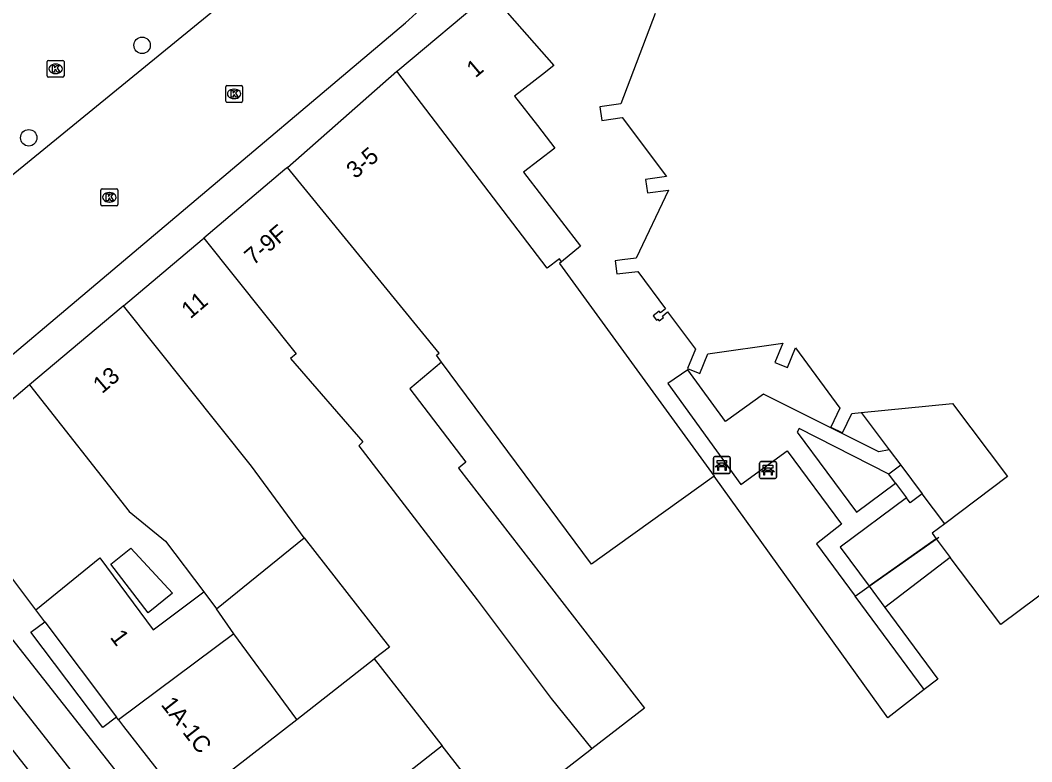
# Model space of a CAD drawing. Extents: x 161087 to 161922, y 382574 to 383873.
# Drawn here: x 161331.9 to 161392, y 383043.5 to 383087.7 of the extents above; entities that cross this region are included whole.
import ezdxf

# ---------------------------------------------------------------- set-up
doc = ezdxf.new("R2010")
doc.units = 0
for name, color, linetype in [('IMGEO_Bank', 7, 'Continuous'), ('IMGEO_Boom', 7, 'Continuous'), ('IMGEO_Erf', 7, 'Continuous'), ('IMGEO_Fietspad_gesloten', 7, 'Continuous'), ('IMGEO_Hek', 7, 'Continuous'), ('IMGEO_Kolk', 7, 'Continuous'), ('IMGEO_OVBaan_gesloten', 7, 'Continuous'), ('IMGEO_Pand', 7, 'Continuous'), ('IMGEO_Pand_nummerreeks', 7, 'Continuous'), ('IMGEO_Rijbaan_lokaal_open', 7, 'Continuous'), ('IMGEO_Voetpad_op_trap', 7, 'Continuous'), ('IMGEO_Voetpad_open', 7, 'Continuous')]:
    doc.layers.add(name, color=color, linetype=linetype)

msp = doc.modelspace()

# ---------------------------------------------------------------- linework, layer by layer
at = {"layer": 'IMGEO_Bank'}
for p, q in [((161373.128, 383060.772), (161373.128, 383061.613)), ((161373.128, 383061.613), (161373.128, 383060.772)), ((161373.203, 383061.697), (161374.044, 383061.697)), ((161374.044, 383061.697), (161373.203, 383061.697)), ((161373.437, 383061.203), (161373.437, 383061.309)), ((161373.481, 383061.309), (161373.481, 383061.203)), ((161373.769, 383061.315), (161373.487, 383061.315)), ((161373.487, 383061.197), (161373.769, 383061.197)), ((161373.775, 383061.203), (161373.775, 383061.309)), ((161373.819, 383061.309), (161373.819, 383061.203)), ((161374.128, 383061.622), (161374.128, 383060.781)), ((161374.128, 383060.781), (161374.128, 383061.622)), ((161375.873, 383060.476), (161375.873, 383061.317)), ((161375.873, 383061.317), (161375.873, 383060.476)), ((161375.948, 383061.401), (161376.789, 383061.401)), ((161376.789, 383061.401), (161375.948, 383061.401)), ((161376.873, 383061.326), (161376.873, 383060.485)), ((161376.873, 383060.485), (161376.873, 383061.326)), ((161374.053, 383060.697), (161373.212, 383060.697)), ((161373.212, 383060.697), (161374.053, 383060.697)), ((161373.825, 383061.095), (161373.432, 383061.095)), ((161376.57, 383060.799), (161376.177, 383060.799)), ((161376.182, 383060.907), (161376.182, 383061.013)), ((161376.226, 383061.013), (161376.226, 383060.907)), ((161376.514, 383061.019), (161376.232, 383061.019)), ((161376.232, 383060.901), (161376.514, 383060.901)), ((161376.52, 383060.907), (161376.52, 383061.013)), ((161376.564, 383061.013), (161376.564, 383060.907)), ((161376.798, 383060.401), (161375.957, 383060.401)), ((161375.957, 383060.401), (161376.798, 383060.401))]:
    msp.add_line(p, q, dxfattribs=at)
for points in [[(161373.375, 383061.095), (161373.233, 383061.095), (161373.345, 383061.197), (161373.431, 383061.197)], [(161373.431, 383061.315), (161373.345, 383061.315), (161373.345, 383061.476), (161373.908, 383061.476), (161373.908, 383061.315), (161373.825, 383061.315)], [(161373.825, 383061.197), (161373.908, 383061.197), (161374.02, 383061.095), (161373.881, 383061.095)], [(161376.176, 383061.019), (161376.09, 383061.019), (161376.09, 383061.18), (161376.653, 383061.18), (161376.653, 383061.019), (161376.57, 383061.019)], [(161373.425, 383061.088), (161373.425, 383060.881), (161373.382, 383060.881), (161373.382, 383061.088)], [(161373.875, 383061.088), (161373.875, 383060.881), (161373.831, 383060.881), (161373.831, 383061.088)], [(161376.12, 383060.799), (161375.978, 383060.799), (161376.09, 383060.901), (161376.176, 383060.901)], [(161376.17, 383060.792), (161376.17, 383060.585), (161376.127, 383060.585), (161376.127, 383060.792)], [(161376.57, 383060.901), (161376.653, 383060.901), (161376.765, 383060.799), (161376.626, 383060.799)], [(161376.62, 383060.792), (161376.62, 383060.585), (161376.576, 383060.585), (161376.576, 383060.792)]]:
    msp.add_lwpolyline(points, dxfattribs=at)
for centre, radius, start, end in [((161373.206, 383061.619), 0.0779, 92.4484, 184.28452), ((161373.206, 383061.619), 0.0779, 92.4484, 184.28452), ((161373.43, 383061.308), 0.00671, 2.89567, 87.10433), ((161373.43, 383061.204), 0.00671, 272.89567, 357.10433), ((161373.487, 383061.308), 0.00671, 92.89567, 177.10433), ((161373.487, 383061.204), 0.00671, 182.89567, 267.10433), ((161373.769, 383061.308), 0.00671, 2.89567, 87.10433), ((161373.769, 383061.204), 0.00671, 272.89567, 357.10433), ((161373.826, 383061.308), 0.00671, 92.89567, 177.10433), ((161373.826, 383061.204), 0.00671, 182.89567, 267.10433), ((161374.05, 383061.619), 0.0779, 2.4484, 94.28452), ((161374.05, 383061.619), 0.0779, 2.4484, 94.28452), ((161375.951, 383061.323), 0.0779, 92.4484, 184.28452), ((161375.951, 383061.323), 0.0779, 92.4484, 184.28452), ((161376.795, 383061.323), 0.0779, 2.4484, 94.28452), ((161376.795, 383061.323), 0.0779, 2.4484, 94.28452), ((161373.206, 383060.775), 0.0779, 182.4484, 274.28452), ((161373.206, 383060.775), 0.0779, 182.4484, 274.28452), ((161373.375, 383061.088), 0.00671, 2.89567, 87.10433), ((161373.432, 383061.088), 0.00671, 92.89567, 177.10433), ((161373.824, 383061.088), 0.00671, 2.89567, 87.10433), ((161373.881, 383061.088), 0.00671, 92.89567, 177.10433), ((161374.05, 383060.775), 0.0779, 272.4484, 4.28452), ((161374.05, 383060.775), 0.0779, 272.4484, 4.28452), ((161376.12, 383060.792), 0.00671, 2.89567, 87.10433), ((161376.177, 383060.792), 0.00671, 92.89567, 177.10433), ((161376.175, 383061.012), 0.00671, 2.89567, 87.10433), ((161376.175, 383060.908), 0.00671, 272.89567, 357.10433), ((161376.232, 383061.012), 0.00671, 92.89567, 177.10433), ((161376.232, 383060.908), 0.00671, 182.89567, 267.10433), ((161376.514, 383061.012), 0.00671, 2.89567, 87.10433), ((161376.514, 383060.908), 0.00671, 272.89567, 357.10433), ((161376.571, 383061.012), 0.00671, 92.89567, 177.10433), ((161376.571, 383060.908), 0.00671, 182.89567, 267.10433), ((161376.569, 383060.792), 0.00671, 2.89567, 87.10433), ((161376.626, 383060.792), 0.00671, 92.89567, 177.10433), ((161375.951, 383060.479), 0.0779, 182.4484, 274.28452), ((161375.951, 383060.479), 0.0779, 182.4484, 274.28452), ((161376.795, 383060.479), 0.0779, 272.4484, 4.28452), ((161376.795, 383060.479), 0.0779, 272.4484, 4.28452)]:
    msp.add_arc(centre, radius, start, end, dxfattribs=at)
at = {"layer": 'IMGEO_Boom'}
for centre in [(161339.171, 383086.168), (161332.433, 383080.665)]:
    msp.add_circle(centre, 0.489, dxfattribs=at)
at = {"layer": 'IMGEO_Erf'}
for points in [[(161385.659, 383047.841), (161383.485, 383046.163), (161373.165, 383060.545)], [(161386.374, 383056.804), (161382.388, 383053.982)], [(161387.204, 383055.697), (161383.319, 383052.72)]]:
    msp.add_lwpolyline(points, dxfattribs=at)
at = {"layer": 'IMGEO_Fietspad_gesloten'}
for points in [[(161412.674, 382945.831), (161395.778, 382967.851), (161371.138, 383000), (161360.861, 383013.409), (161355.304, 383020.491), (161354.659, 383021.314), (161325.561, 383058.315)], [(161323.08, 383057.943), (161323.199, 383057.888), (161324.605, 383056.158), (161359.235, 383012.056), (161368.52, 383000), (161387, 382976.004), (161387.474, 382975.438), (161388.128, 382974.526), (161389.409, 382972.718), (161389.945, 382971.934)]]:
    msp.add_lwpolyline(points, dxfattribs=at)
at = {"layer": 'IMGEO_Hek'}
for points in [[(161382.388, 383053.982), (161386.53, 383056.914)], [(161381.549, 383053.388), (161382.388, 383053.982)]]:
    msp.add_lwpolyline(points, dxfattribs=at)
at = {"layer": 'IMGEO_Kolk'}
for p, q in [((161333.529, 383084.343), (161333.529, 383085.195)), ((161333.604, 383085.269), (161334.456, 383085.269)), ((161334.53, 383085.195), (161334.53, 383084.343)), ((161334.017, 383085.049), (161334.042, 383085.049)), ((161334.456, 383084.269), (161333.604, 383084.269)), ((161334.04, 383084.489), (161334.015, 383084.489)), ((161344.139, 383082.848), (161344.139, 383083.7)), ((161344.214, 383083.774), (161345.066, 383083.774)), ((161344.627, 383083.554), (161344.652, 383083.554)), ((161345.14, 383083.7), (161345.14, 383082.848)), ((161345.066, 383082.774), (161344.214, 383082.774)), ((161344.65, 383082.994), (161344.625, 383082.994)), ((161336.722, 383076.698), (161336.722, 383077.55)), ((161336.797, 383077.624), (161337.649, 383077.624)), ((161337.21, 383077.404), (161337.235, 383077.404)), ((161337.723, 383077.55), (161337.723, 383076.698)), ((161337.233, 383076.844), (161337.208, 383076.844)), ((161337.649, 383076.624), (161336.797, 383076.624))]:
    msp.add_line(p, q, dxfattribs=at)
for points in [[(161333.529, 383084.343), (161333.529, 383085.195)], [(161333.604, 383085.269), (161334.456, 383085.269)], [(161334.53, 383085.195), (161334.53, 383084.343)], [(161333.85, 383084.969), (161333.973, 383084.969), (161333.973, 383084.818), (161334.103, 383084.969), (161334.267, 383084.969), (161334.121, 383084.818), (161334.274, 383084.569), (161334.122, 383084.569), (161334.037, 383084.733), (161333.973, 383084.666), (161333.973, 383084.569), (161333.85, 383084.569), (161333.85, 383084.969)], [(161334.456, 383084.269), (161333.604, 383084.269)], [(161344.139, 383082.848), (161344.139, 383083.7)], [(161344.214, 383083.774), (161345.066, 383083.774)], [(161344.46, 383083.474), (161344.583, 383083.474), (161344.583, 383083.323), (161344.713, 383083.474), (161344.877, 383083.474), (161344.731, 383083.323), (161344.884, 383083.074), (161344.732, 383083.074), (161344.647, 383083.238), (161344.583, 383083.171), (161344.583, 383083.074), (161344.46, 383083.074), (161344.46, 383083.474)], [(161345.14, 383083.7), (161345.14, 383082.848)], [(161345.066, 383082.774), (161344.214, 383082.774)], [(161336.722, 383076.698), (161336.722, 383077.55)], [(161336.797, 383077.624), (161337.649, 383077.624)], [(161337.723, 383077.55), (161337.723, 383076.698)], [(161337.043, 383077.324), (161337.166, 383077.324), (161337.166, 383077.173), (161337.296, 383077.324), (161337.46, 383077.324), (161337.314, 383077.173), (161337.467, 383076.924), (161337.315, 383076.924), (161337.23, 383077.088), (161337.166, 383077.021), (161337.166, 383076.924), (161337.043, 383076.924), (161337.043, 383077.324)], [(161337.649, 383076.624), (161336.797, 383076.624)]]:
    msp.add_lwpolyline(points, dxfattribs=at)
for centre, start, end in [((161333.606, 383085.193), 91.55205, 178.44795), ((161333.606, 383085.193), 91.55205, 178.44795), ((161334.454, 383085.193), 1.55205, 88.44795), ((161334.454, 383085.193), 1.55205, 88.44795), ((161333.606, 383084.345), 181.55205, 268.44795), ((161333.606, 383084.345), 181.55205, 268.44795), ((161334.454, 383084.345), 271.55205, 358.44795), ((161334.454, 383084.345), 271.55205, 358.44795), ((161344.216, 383083.698), 91.55205, 178.44795), ((161344.216, 383083.698), 91.55205, 178.44795), ((161345.064, 383083.698), 1.55205, 88.44795), ((161345.064, 383083.698), 1.55205, 88.44795), ((161344.216, 383082.85), 181.55205, 268.44795), ((161344.216, 383082.85), 181.55205, 268.44795), ((161345.064, 383082.85), 271.55205, 358.44795), ((161345.064, 383082.85), 271.55205, 358.44795), ((161336.799, 383077.548), 91.55205, 178.44795), ((161336.799, 383077.548), 91.55205, 178.44795), ((161337.647, 383077.548), 1.55205, 88.44795), ((161337.647, 383077.548), 1.55205, 88.44795), ((161336.799, 383076.7), 181.55205, 268.44795), ((161336.799, 383076.7), 181.55205, 268.44795), ((161337.647, 383076.7), 271.55205, 358.44795), ((161337.647, 383076.7), 271.55205, 358.44795)]:
    msp.add_arc(centre, 0.0765, start, end, dxfattribs=at)
for centre, major_axis, ratio, start_param, end_param in [((161334.016, 383084.769), (-0.387, 0.002), 0.722429, 4.712389, 7.853982), ((161334.041, 383084.769), (-0.39, 0.002), 0.717154, 1.570796, 4.712389), ((161344.626, 383083.274), (-0.387, 0.002), 0.722429, 4.712389, 7.853982), ((161344.651, 383083.274), (-0.39, 0.002), 0.717154, 1.570796, 4.712389), ((161337.209, 383077.124), (-0.387, 0.002), 0.722429, 4.712389, 7.853982), ((161337.234, 383077.124), (-0.39, 0.002), 0.717154, 1.570796, 4.712389)]:
    msp.add_ellipse(centre, major_axis=major_axis, ratio=ratio, start_param=start_param, end_param=end_param, dxfattribs=at)
at = {"layer": 'IMGEO_OVBaan_gesloten'}
msp.add_lwpolyline([(161325.438, 383051.889), (161366.206, 383000), (161367.365, 382998.522)], dxfattribs=at)
at = {"layer": 'IMGEO_Pand'}
for points in [[(161354.318, 383084.62), (161354.364, 383084.66), (161359.849, 383089.298), (161359.918, 383089.219)], [(161360.142, 383088.963), (161363.648, 383084.959), (161362.972, 383084.424), (161361.312, 383083.146), (161362.666, 383081.388), (161363.693, 383080.054), (161361.831, 383078.62), (161365.218, 383074.222), (161364.102, 383073.291)], [(161369.672, 383088.069), (161367.615, 383082.684), (161366.374, 383082.507), (161366.491, 383081.698), (161367.707, 383081.87), (161370.346, 383078.36), (161369.097, 383078.186), (161369.202, 383077.393), (161370.45, 383077.552), (161368.539, 383073.5), (161367.695, 383073.4), (161367.286, 383073.351), (161367.382, 383072.564), (161368.636, 383072.712), (161370.282, 383070.486), (161369.976, 383070.26), (161369.905, 383070.357), (161369.549, 383070.072), (161369.741, 383069.814), (161369.825, 383069.874), (161369.893, 383069.782), (161370.152, 383069.98), (161370.091, 383070.059), (161370.396, 383070.304), (161372.056, 383068.092), (161371.586, 383066.932), (161372.327, 383066.643), (161372.794, 383067.808), (161377.262, 383068.452), (161376.786, 383067.307), (161377.528, 383066.999), (161378, 383068.171), (161380.648, 383064.59), (161380.099, 383063.452), (161380.806, 383063.112), (161381.357, 383064.263), (161381.903, 383064.319)], [(161347.804, 383078.905), (161354.318, 383084.62)], [(161364.102, 383073.291), (161363.972, 383073.474), (161363.242, 383072.901), (161354.318, 383084.62)], [(161347.804, 383078.905), (161347.663, 383078.781), (161342.835, 383074.693)], [(161356.973, 383067.319), (161356.673, 383067.725), (161356.825, 383067.846), (161347.804, 383078.905)], [(161338.071, 383070.66), (161342.739, 383074.613), (161342.835, 383074.693)], [(161342.835, 383074.693), (161348.322, 383067.806), (161347.987, 383067.529), (161352.289, 383062.57), (161352.053, 383062.349), (161359.093, 383053.183), (161363.477, 383047.313), (161365.909, 383044.313)], [(161364.102, 383073.291), (161363.982, 383073.191), (161373.165, 383060.545)], [(161338.071, 383070.66), (161337.93, 383070.541), (161332.485, 383065.961)], [(161348.807, 383056.868), (161345.668, 383061.123), (161338.071, 383070.66)], [(161356.973, 383067.319), (161355.077, 383065.731), (161358.407, 383061.359), (161357.97, 383061.02), (161369.037, 383046.737), (161365.909, 383044.313)], [(161373.165, 383060.545), (161366.508, 383055.762), (161365.873, 383055.306), (161356.973, 383067.319)], [(161332.485, 383065.961), (161330.317, 383064.136), (161330.489, 383063.928), (161328.256, 383062.101), (161328.085, 383062.31), (161327.199, 383061.585)], [(161332.485, 383065.961), (161338.407, 383058.427), (161340.56, 383056.66), (161342.833, 383053.65)], [(161381.903, 383064.319), (161387.333, 383064.867), (161390.608, 383060.509), (161386.875, 383057.703)], [(161332.856, 383052.582), (161326.89, 383060.523)], [(161386.875, 383057.703), (161386.123, 383057.138), (161386.374, 383056.804)], [(161343.591, 383052.648), (161348.807, 383056.868)], [(161348.807, 383056.868), (161353.875, 383050.364), (161352.97, 383049.659)], [(161386.374, 383056.804), (161387.204, 383055.697)], [(161339.528, 383052.405), (161337.303, 383055.304), (161338.497, 383056.247), (161340.972, 383053.567), (161339.528, 383052.405)], [(161332.856, 383052.582), (161336.652, 383055.677), (161339.838, 383051.391), (161342.833, 383053.65)], [(161393.488, 383054.156), (161390.203, 383051.702), (161387.204, 383055.697)], [(161342.833, 383053.65), (161343.591, 383052.648)], [(161333.386, 383051.877), (161332.856, 383052.582)], [(161344.621, 383051.158), (161343.591, 383052.648)], [(161333.386, 383051.877), (161337.649, 383046.199)], [(161344.621, 383051.158), (161337.774, 383046.032)], [(161348.36, 383046.066), (161344.621, 383051.158)], [(161348.36, 383046.066), (161352.97, 383049.659)], [(161352.97, 383049.659), (161357.01, 383044.483)], [(161337.774, 383046.032), (161337.649, 383046.199)], [(161337.774, 383046.032), (161338.067, 383045.642), (161341.754, 383040.918)], [(161341.754, 383040.918), (161348.36, 383046.066)], [(161357.01, 383044.483), (161345.825, 383035.703)], [(161360.44, 383040.09), (161357.01, 383044.483)], [(161365.909, 383044.313), (161365.785, 383044.217), (161360.786, 383040.357), (161360.44, 383040.09)]]:
    msp.add_lwpolyline(points, dxfattribs=at)
at = {"layer": 'IMGEO_Rijbaan_lokaal_open'}
for points in [[(161357.76, 383102.637), (161353.934, 383096.833), (161331.379, 383078.376), (161324.754, 383073.591), (161319.89, 383069.645)], [(161325.261, 383062.484), (161325.595, 383062.843), (161354.821, 383087.495)]]:
    msp.add_lwpolyline(points, dxfattribs=at)
msp.add_arc((161326.347, 383119.226), 42.634, 311.9039, 318.04286, dxfattribs=at)
at = {"layer": 'IMGEO_Voetpad_op_trap'}
for points in [[(161383.951, 383060.118), (161383.557, 383060.664)], [(161385.539, 383059.48), (161384.823, 383058.949), (161384.604, 383059.243)]]:
    msp.add_lwpolyline(points, dxfattribs=at)
at = {"layer": 'IMGEO_Voetpad_open'}
for points in [[(161383.575, 383062.094), (161382.96, 383061.991), (161376.11, 383065.423), (161373.837, 383063.792), (161371.615, 383066.854), (161370.412, 383066.053), (161374.759, 383060.042), (161377.502, 383062.041), (161380.749, 383057.673), (161379.25, 383056.501), (161381.549, 383053.388)], [(161381.903, 383064.319), (161383.575, 383062.094)], [(161383.557, 383060.664), (161378.215, 383063.363), (161378.102, 383063.156), (161381.64, 383058.402), (161383.951, 383060.118)], [(161383.575, 383062.094), (161384.262, 383061.18)], [(161384.262, 383061.18), (161383.557, 383060.664)], [(161384.262, 383061.18), (161385.539, 383059.48)], [(161383.951, 383060.118), (161384.604, 383059.243)], [(161386.875, 383057.703), (161385.539, 383059.48)], [(161384.604, 383059.243), (161380.665, 383056.319), (161382.388, 383053.982)], [(161381.549, 383053.388), (161382.388, 383053.982)], [(161382.388, 383053.982), (161383.319, 383052.72)], [(161385.659, 383047.841), (161381.549, 383053.388)], [(161383.319, 383052.72), (161386.461, 383048.461), (161385.659, 383047.841)], [(161337.649, 383046.199), (161336.841, 383045.59), (161332.554, 383051.249), (161333.386, 383051.877)]]:
    msp.add_lwpolyline(points, dxfattribs=at)

# ---------------------------------------------------------------- texts
at = {"layer": 'IMGEO_Pand_nummerreeks'}
for s, rotation, p in [('1', 40.13664, (161358.983, 383084.195)), ('3-5', 40.32618, (161351.841, 383078.183)), ('7-9F', 40.32618, (161345.784, 383073.041)), ('11', 40.32618, (161342.034, 383069.858)), ('13', 40.32618, (161336.785, 383065.402)), ('1', 306.83775, (161337.231, 383050.945)), ('1A-1C', 307.97324, (161340.255, 383046.934))]:
    msp.add_text(s, height=1, rotation=rotation, dxfattribs=at).set_placement(p)

doc.saveas('drawing.dxf')
